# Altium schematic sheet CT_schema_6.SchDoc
size 349 x 348 mm
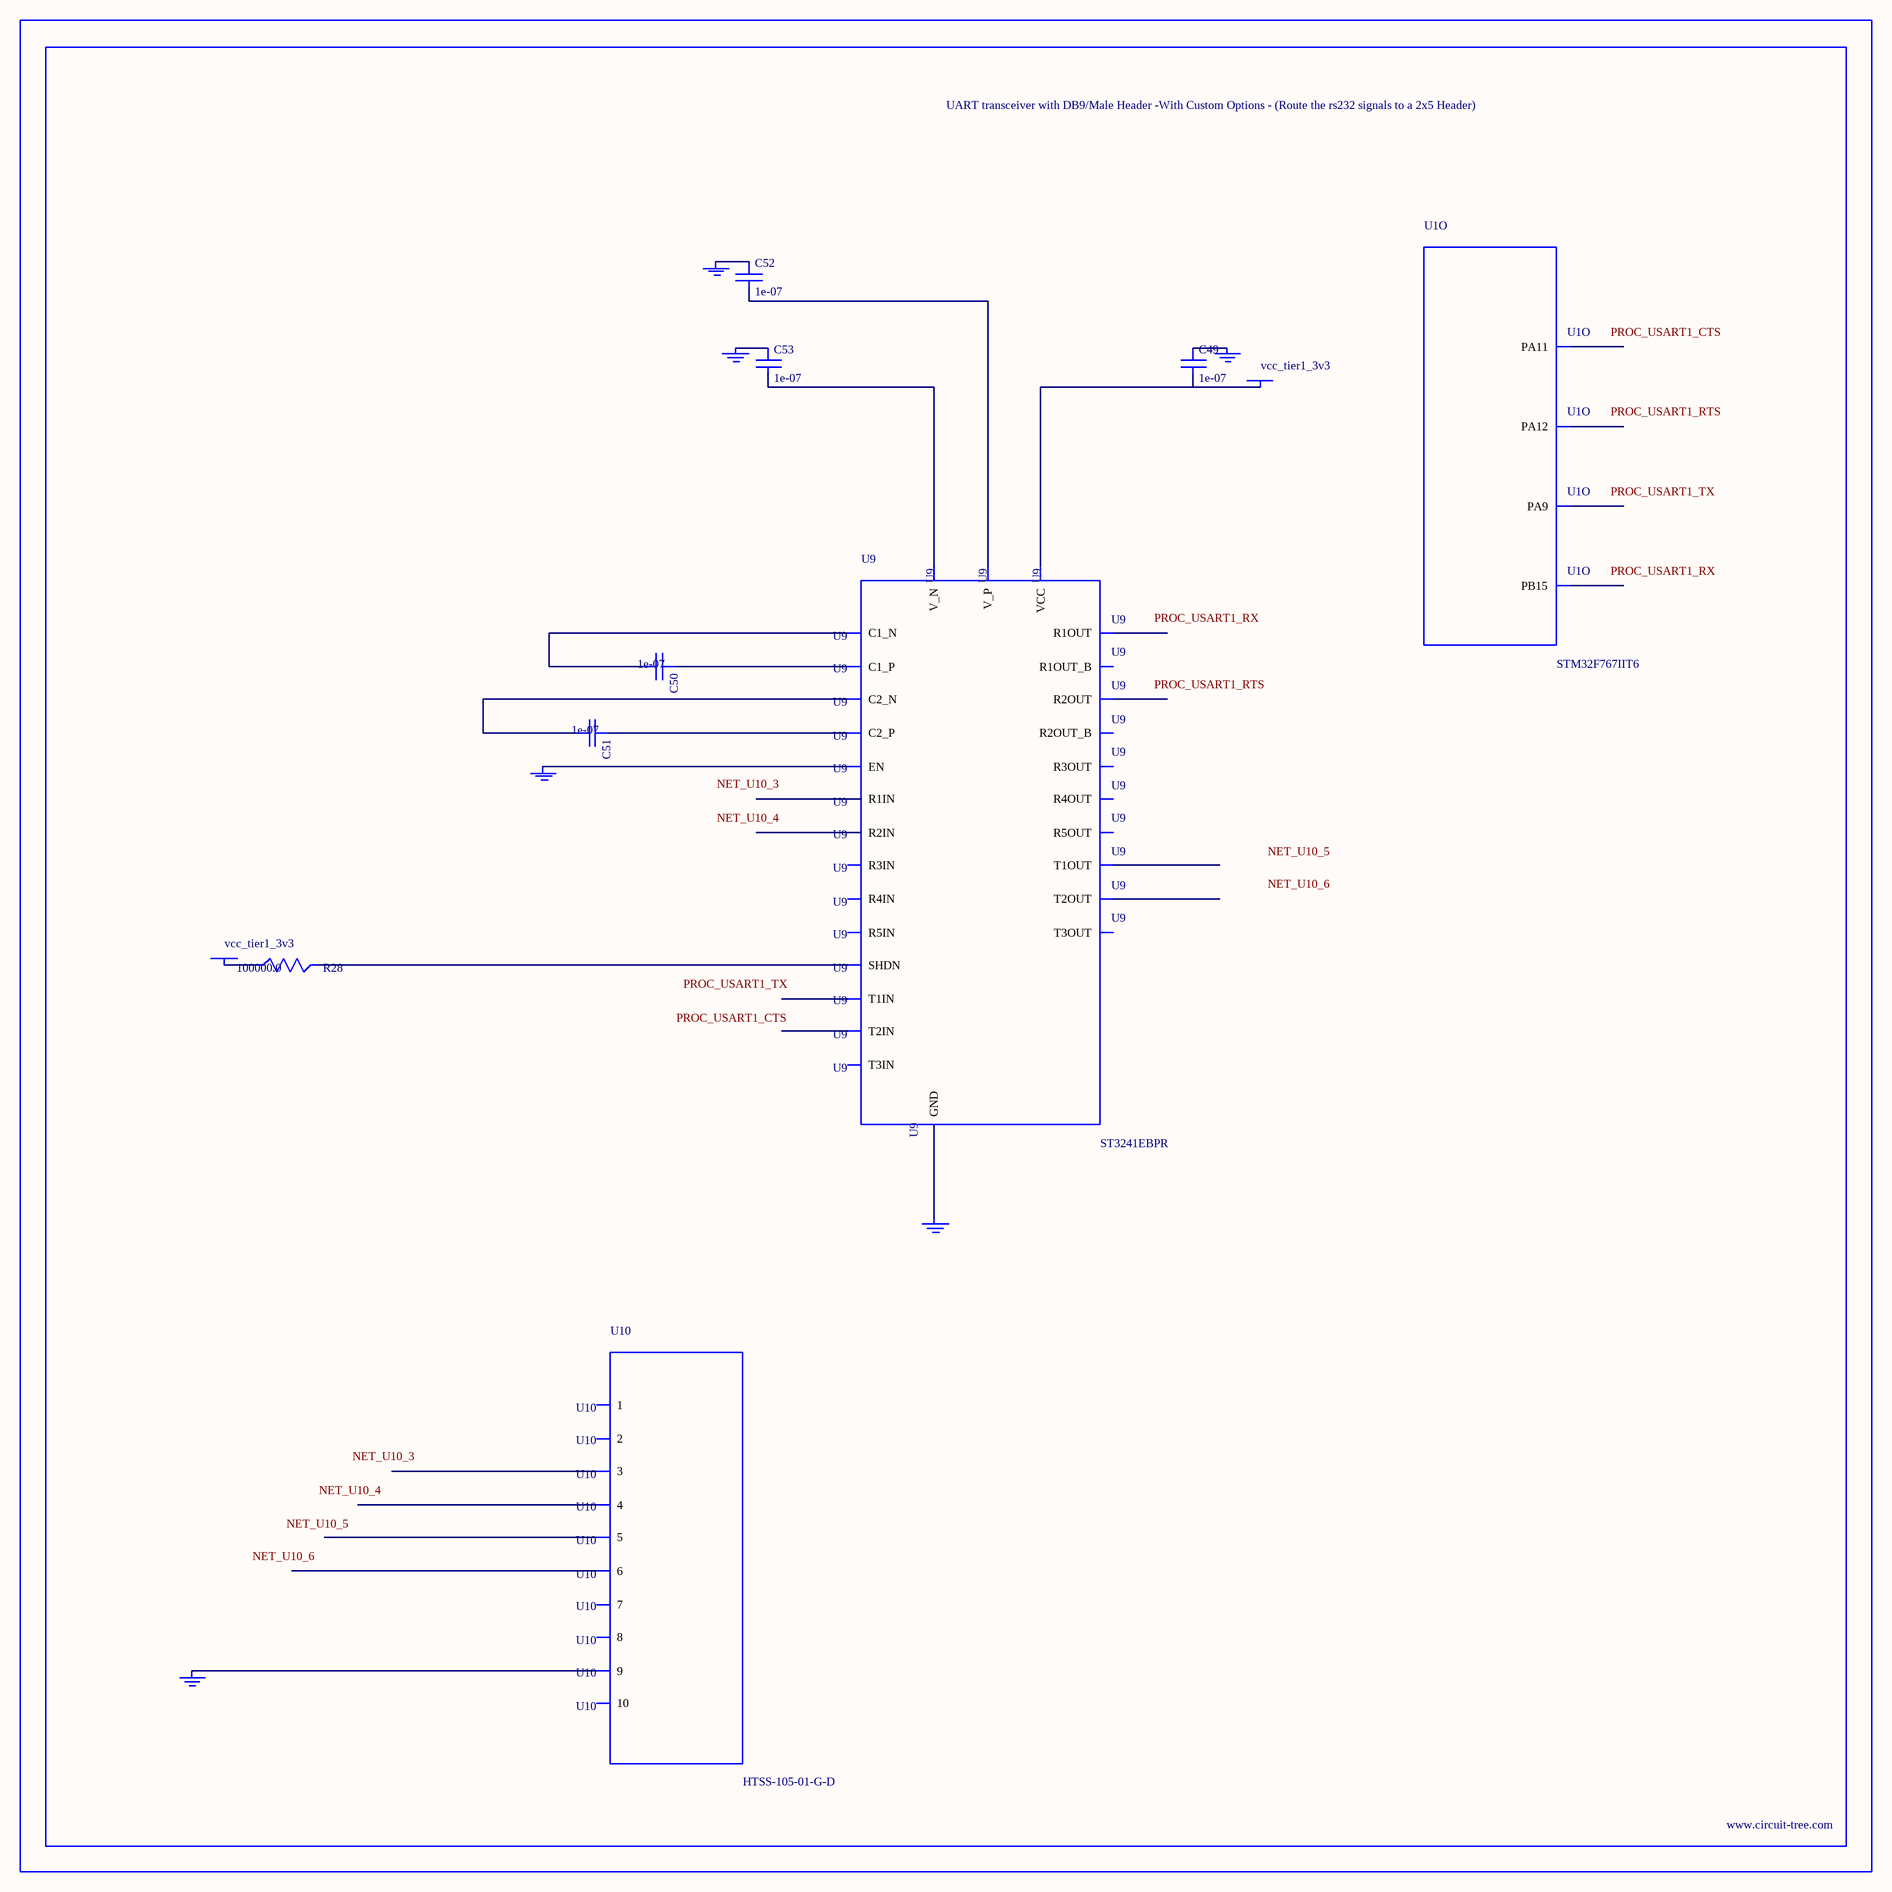
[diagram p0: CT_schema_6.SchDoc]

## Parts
BORDER5  (no value)
C49  1e-07  [C0402]
C50  1e-07  [C0402]
C51  1e-07  [C0402]
C52  1e-07  [C0402]
C53  1e-07  [C0402]
GND_INSTANCE_5_0  (no value)
GND_INSTANCE_5_1  (no value)
GND_INSTANCE_5_2  (no value)
GND_INSTANCE_5_3  (no value)
GND_INSTANCE_5_4  (no value)
GND_INSTANCE_5_5  (no value)
POWER_INSTANCE_5_0  vcc_tier1_3v3
POWER_INSTANCE_5_1  vcc_tier1_3v3
R28  100000.0  [R0603]
U1  STM32F767IIT6  [LQFP176]  (part O of 15)
U9  ST3241EBPR  [SSOP-28]
U10  HTSS-105-01-G-D  [HTSS-105-01-G-D]

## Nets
NetC49_1: C49.1 GND_INSTANCE_5_2.0(GND)
NetC49_2: C49.2 POWER_INSTANCE_5_1.0(PWR) U9.26(VCC)
NetC50_1: C50.1 U9.28(C1_P)
NetC50_2: C50.2 U9.24(C1_N)
NetC51_1: C51.1 U9.1(C2_P)
NetC51_2: C51.2 U9.2(C2_N)
NetC52_1: C52.1 GND_INSTANCE_5_3.0(GND)
NetC52_2: C52.2 U9.27(V_P)
NetC53_1: C53.1 GND_INSTANCE_5_0.0(GND)
NetC53_2: C53.2 U9.3(V_N)
NetGND_INSTANCE_5_1_0: GND_INSTANCE_5_1.0(GND) U9.23(EN)
NetGND_INSTANCE_5_4_0: GND_INSTANCE_5_4.0(GND) U9.25(GND)
NetGND_INSTANCE_5_5_0: GND_INSTANCE_5_5.0(GND) U10.9
NetPOWER_INSTANCE_5_0_0: POWER_INSTANCE_5_0.0(PWR) R28.1
NetR28_2: R28.2 U9.22(SHDN)

Not connected (* = marked no-connect by the designer): U1 95(PB15) 120(PA9) 122(PA11) 123(PA12); U9 4(R1IN) 5(R2IN) 6(R3IN) 7(R4IN) 8(R5IN) 9(T1OUT) 10(T2OUT) 11(T3OUT) 12(T3IN) 13(T2IN) 14(T1IN) 15(R5OUT) 16(R4OUT) 17(R3OUT) 18(R2OUT) 19(R1OUT) 20(R2OUT_B) 21(R1OUT_B); U10 1 2 3 4 5 6 7 8 10

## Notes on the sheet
- Labels drawn without touching a wire or pin: NET_U10_3, NET_U10_4, NET_U10_5, NET_U10_6, PROC_USART1_CTS, PROC_USART1_RTS, PROC_USART1_RX, PROC_USART1_TX

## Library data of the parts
BORDER5 = BORDER_PAGE5
C49-C53 = C0402C104K3RACTU
GND_INSTANCE_5_0-GND_INSTANCE_5_5 = GND
POWER_INSTANCE_5_0 POWER_INSTANCE_5_1 = PWR
R28 = RC0603JR-07100KL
